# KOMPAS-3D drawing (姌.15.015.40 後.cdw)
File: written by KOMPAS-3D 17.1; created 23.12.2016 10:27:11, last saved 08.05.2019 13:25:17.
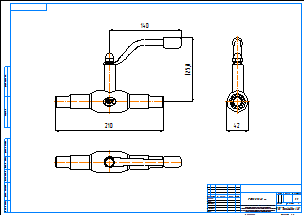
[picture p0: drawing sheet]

Sheet 1: A2, landscape

Title block, sheet 1: name: КШ.15.015.40 сс; material: Внимание! Данный продукт является объектом авторского права ООО «Торговый Дом АДЛ». / Запрещается изменение, копирование, распространение / (в том числе путем копирования на другие сайты и ресурсы в Интернете) / или любое иное использование информации и объектов без предварительного / согласия правообладателя (ООО «Торговый Дом АДЛ»).; sheets: 1; organisation: ООО "Торговый дом АДЛ"; sheet format: A2; stored path: C:\Users\tra\Desktop\2д чертежи\Шаровые краны БИВАЛ\КШ_Бивал_серия_14_15\KOMPAS_2D\КШ.15.015.40 сс.cdw

Views: Вид 1, Проекционный вид 2, Проекционный вид 3
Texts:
  Klimkovich
  ADL
Dimensions and other numbers on the sheet: 210; 125,8; 140; 42; 1:1; 1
